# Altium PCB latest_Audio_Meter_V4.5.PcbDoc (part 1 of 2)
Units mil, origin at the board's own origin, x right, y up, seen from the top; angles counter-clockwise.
Board outline 2756.14 x 2519.69 mil, 2 copper layers (Top Layer, Bottom Layer), stack 57.087 mil thick; 115 components, 61 nets, 352 pads, 1177 vias.
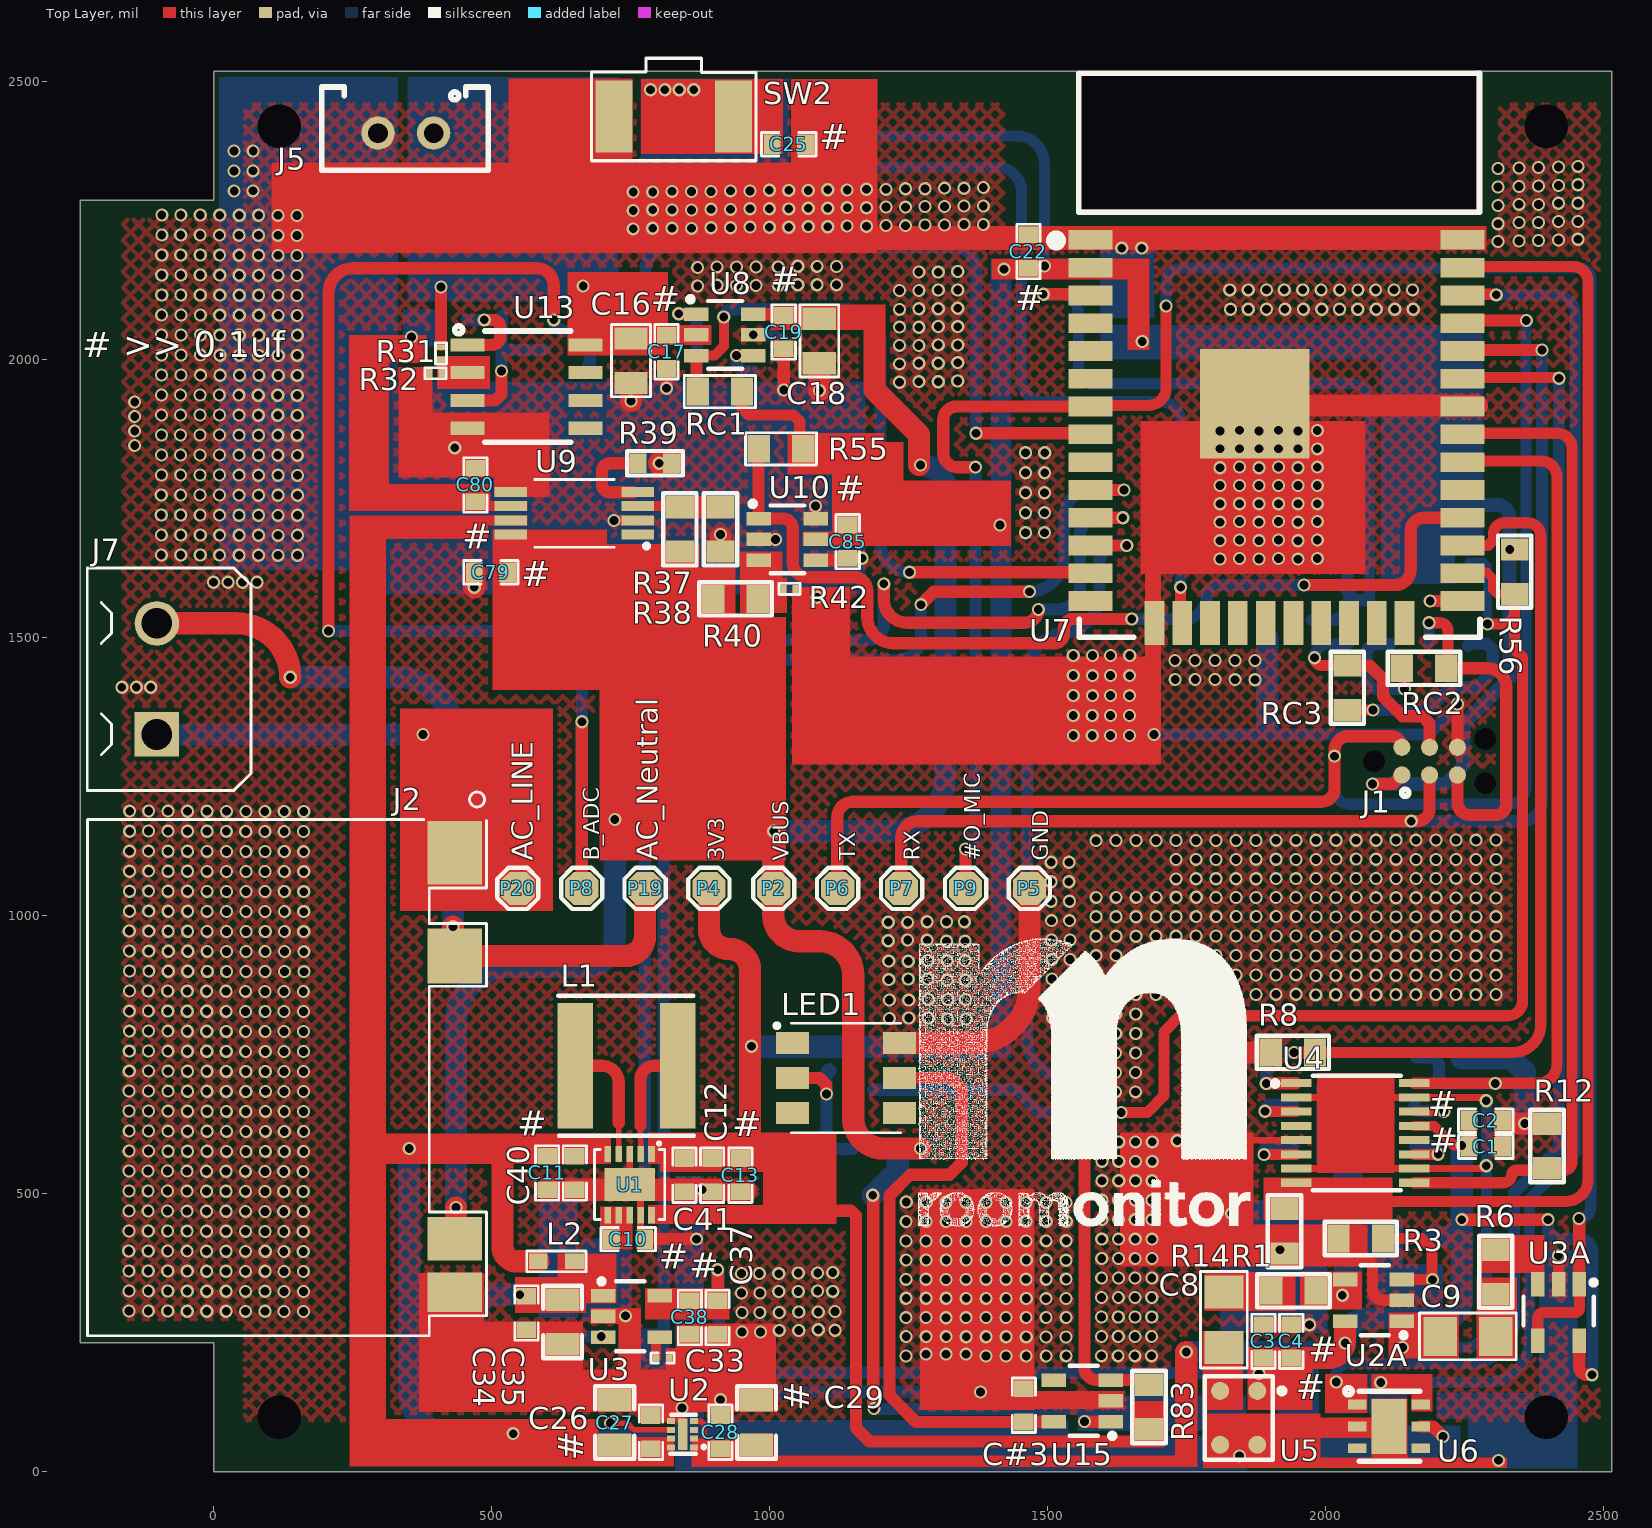
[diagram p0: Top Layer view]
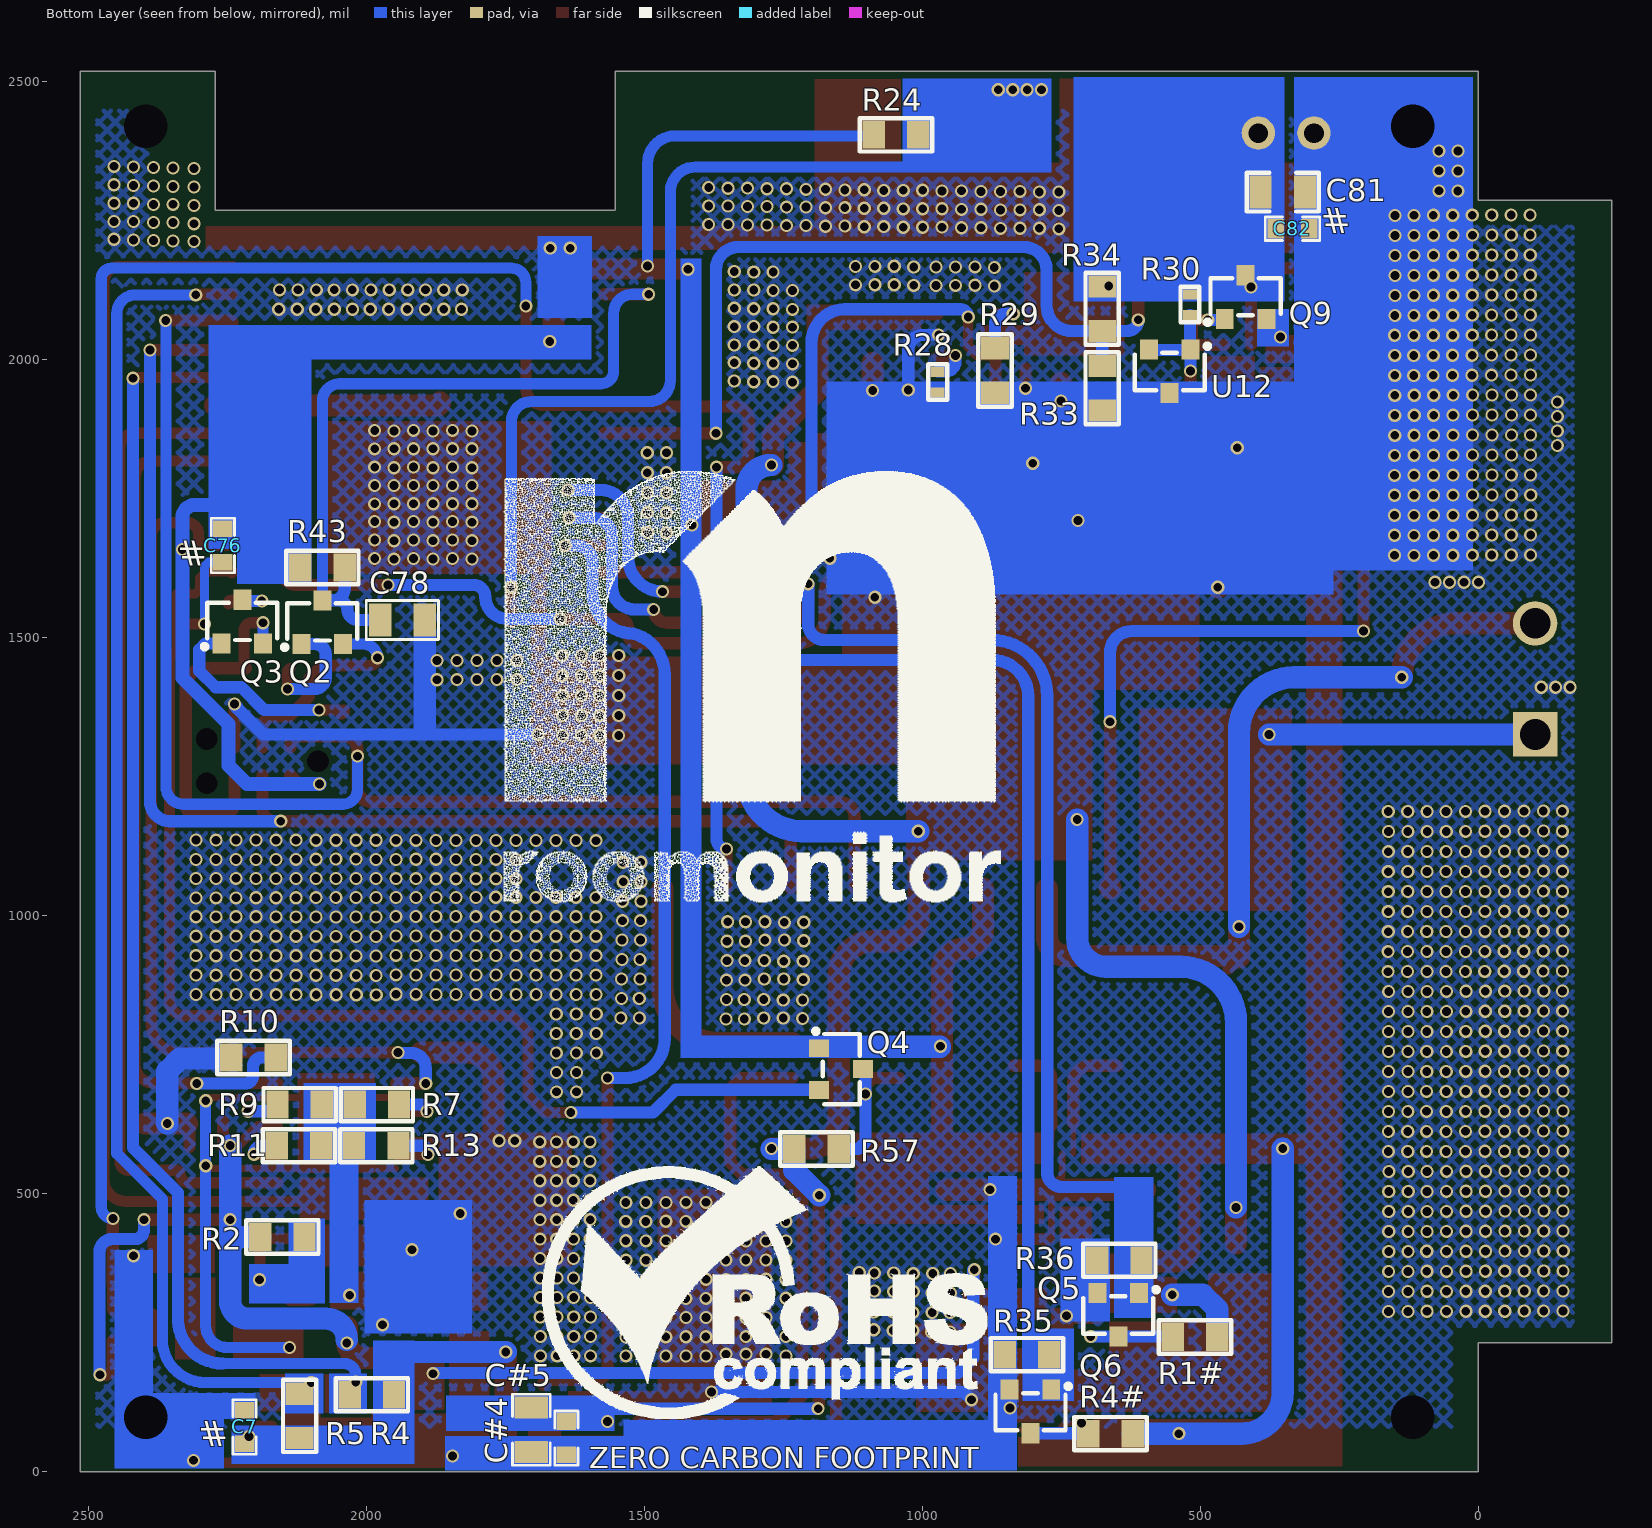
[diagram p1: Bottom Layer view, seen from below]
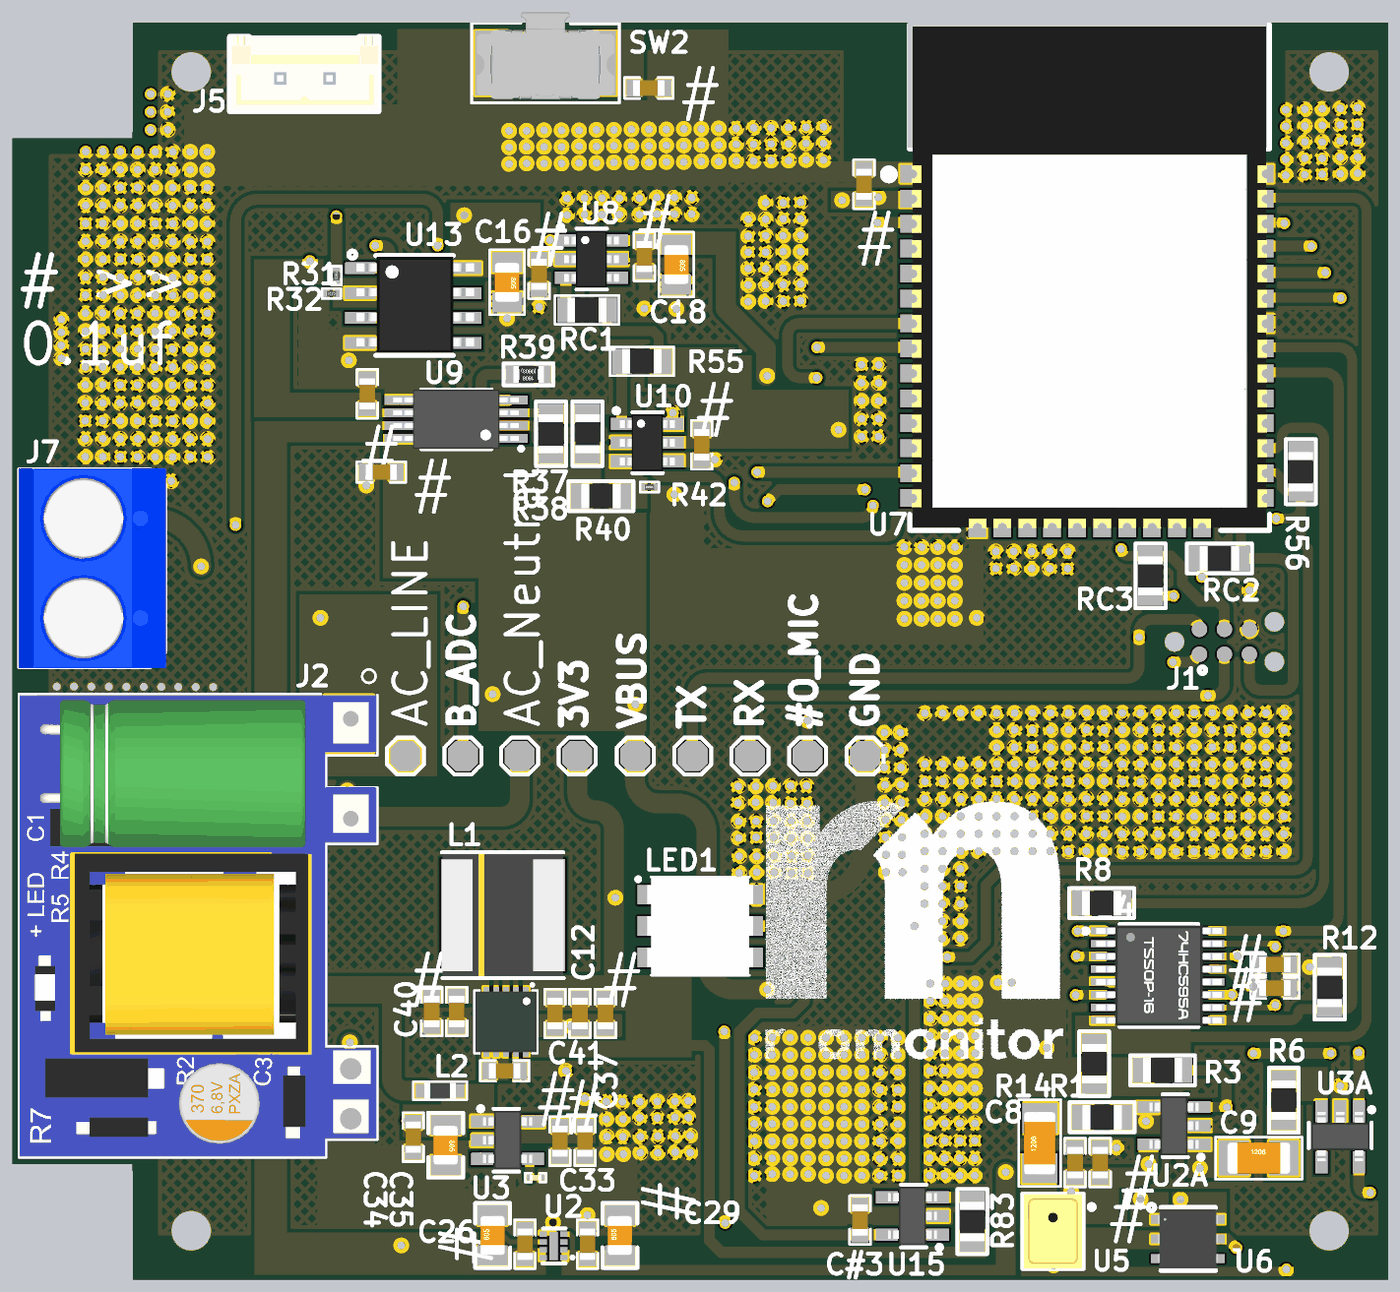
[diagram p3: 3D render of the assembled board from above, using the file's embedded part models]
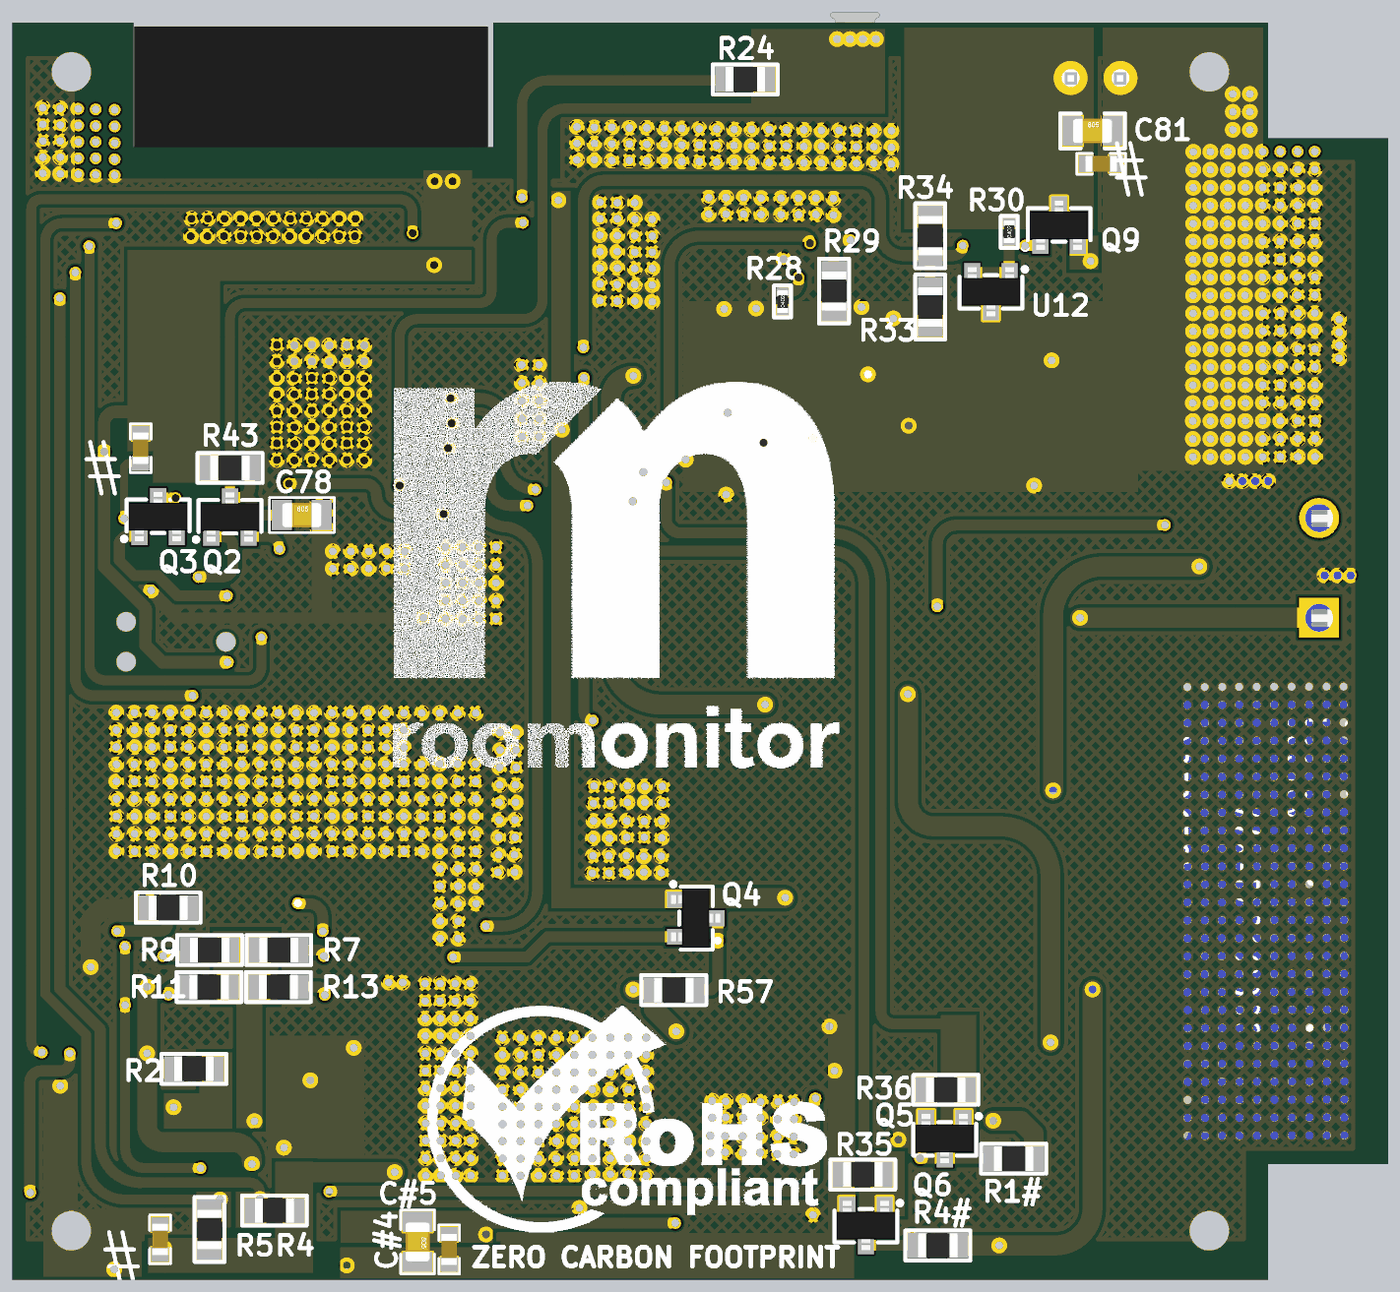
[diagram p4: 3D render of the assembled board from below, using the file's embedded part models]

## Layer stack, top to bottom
Top Solder: solder mask 2.7559, Solder Resist, Dk 3.5
Top Layer: signal copper 13.7795
Dielectric 1: dielectric 29.5276, FR-4, Dk 4.8
Bottom Layer: signal copper 13.7795
Bottom Solder: solder mask 3.1496, Solder Resist, Dk 3.5

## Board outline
-240.16,231.28 -240.16,2287.03 0,2287.03 0,2519 1553,2519 1553,2269 2273,2269 2273,2519 2515.98,2519 2515.98,-0.68 0,-0.69 0,231.28

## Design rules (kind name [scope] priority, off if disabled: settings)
Clearance [All] p1: gap=7 ignorepadtopadclearanceinfootprint=FALSE except(3: Arc-SMDPad Track-SMDPad SMDPad-SMDPad)
ComponentClearance [All] p1: gap=0 collisioncheckmode=3 verticalgap=0 showdistances=FALSE
MinimumSolderMaskSliver [All] p1: minsoldermaskwidth=0
PolygonConnect [All] p1: connectstyle=Direct reliefconductorwidth=10 reliefentries=4 polygonreliefangle="90 Angle" airgapwidth=10
RoutingVias [All] p1: holewidth=15.75 width=23.62 viastyle="Through Hole" minholewidth=15.75 minwidth=23.62 maxholewidth=28 maxwidth=50
SilkToSilkClearance [All] p1: silktosilkclearance=0
SilkToSolderMaskClearance [IsPad] p1: minsilkscreentomaskgap=0 clearancetoexposedcopper=TRUE
SolderMaskExpansion [All] p1: expansion=4
Width [All] p1: maxlimit=40 minlimit=8 preferedwidth=22
26 further rules are at their usual default settings.

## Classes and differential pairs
component class U_SourceSelector_Section: C79 C80 C85 R37 R38 R39 R40 R42 R55 U9 U10
component class U_Supply_Section: J2
component class U_Sensor_Section: C7 C#3 C#4 C#5 LED1 R4 R5 R83 U6 U15
component class U_Power_Section: C10 C11 C12 C13 C26 C27 C28 C29 C33 C34 C35 C37 C38 C40 C41 L1 L2 Q5 Q6 R1# R4# R35 R36 U1 U2 U3
component class U_Controller_Section: C22 C25 C76 C78 Q2 Q3 Q4 R24 R43 R56 R57 RC2 RC3 SW2 U7
component class U_Connector_Section: C81 C82 J1 J5 J7 P2 P4 P5 P6 P7 P19 P20
component class "U_Battery management Section": C16 C17 C18 C19 P8 Q9 R28 R29 R30 R31 R32 R33 R34 RC1 U8 U12 U13
component class U_Audio_Section: C1 C2 C3 C4 C8 C9 P9 R1 R2 R3 R6 R7 R8 R9 R10 R11 R12 R13 R14 U2A U3A U4 U5

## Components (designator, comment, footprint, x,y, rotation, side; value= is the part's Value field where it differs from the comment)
C1 "0.1uF" Cap0603 2289,584 r0 top
C2 "0.1uF" Cap0603 2289,631 r0 top
C3 "0.1uF" Cap0603 1889,234 r90 top
C4 "0.1uF" Cap0603 1939,234 r90 top
C7 "0.1uF" Cap0603 2220,80 r90 bottom
C8 "1206YC105K4T2A" Cap1206 1818,273 r90 top
C9 "1206YC105K4T2A" Cap1206 2257,243 r0 top
C10 "0.1uF" Cap0603 746,418 r0 top
C11 "0.1uF" Cap0603 600,537 r270 top
C12 "10uF" Cap0603 897,533 r270 top
C13 "0.1uF" Cap0603 948,533 r270 top
C16 "1uF" Cap0805#1 751,1998.57 r270 top
C17 "0.1uF" Cap0603 815,2014.57 r270 top
C18 "1uF" Cap0805#1 1090,2034 r270 top
C19 "0.1uF" Cap0603 1026,2050 r270 top
C22 "0.1uF" Cap0603 1466,2195 r90 top
C25 "0.1uF" Cap0603 1035,2388 r0 top
C26 "0.1uF" Cap0603 787,70.56 r90 top
C27 "1uF" Cap0805#2 722,88 r90 top
C28 "0.1uF" Cap0603 912,70.56 r90 top
C29 "1uF" Cap0805#2 977,88 r90 top
C33 "10nF" "CAP 0201" 808,204 r0 top
C34 "10uF" Cap0603 563,285 r270 top
C35 "1uF" Cap0805#2 628,269 r270 top
C37 "10uF" Cap0603 907,277 r270 top
C38 "0.1uF" Cap0603 857,277 r270 top
C40 "10uF" Cap0603 650,537 r270 top
C41 "10uF" Cap0603 847,533 r270 top
C76 "0.1uF" Cap0603 2259,1666 r270 bottom
C78 "1uF" Cap0805#1 1936,1532 r180 bottom
C79 "0.1uF" Cap0603 499,1618 r180 top
C80 "0.1uF" Cap0603 471,1775 r90 top
C81 "4.7UF" Cap0805#2 352,2302 r180 bottom
C82 "0.1uF" Cap0603 334.56,2236 r180 bottom
C85 "0.1uF" Cap0603 1141,1673 r270 top
C#3 "0.1uF" Cap0603 1458,119 r90 top
C#4 "1uF" Cap0805#2 1704,75 r270 bottom
C#5 "0.1uF" Cap0603 1641,60 r270 bottom
J1 "TC2030-IDC" TC2030-IDC 2188,1278 r0 top
J2 "SMD Header" "SMD Header" 434.08,721 r90 top
J5 "B2B-EH-A(LF)(SN)" B2B-EH-A(LF)(SN) 346,2408 r180 top
J7 "Terminal Block 2POS" "Terminal Block 2P" -102,1326 r90 top
L1 "NR6028T1R5N" NR6028T1R5N 743,730 r0 top
L2 "BLM18SG121TN1D" "IND 0603" 617,378 r0 top
LED1 "COM-11821" COM-11821 1138,708 r0 top locked
P2 "TEST POINT" "TEST POINT" 1007.75,1049 r180 top
P4 "TEST POINT" "TEST POINT" 891.38,1049 r0 top
P5 "TEST POINT" "TEST POINT" 1468,1049 r0 top
P6 "TEST POINT" "TEST POINT" 1122.81,1049 r0 top
P7 "TEST POINT" "TEST POINT" 1237.88,1049 r0 top
P8 "TEST POINT" "TEST POINT" 662.56,1049 r90 top
P9 "TEST POINT" "TEST POINT" 1352.94,1049 r270 top
P19 "TEST POINT" "TEST POINT" 776.31,1049 r270 top
P20 "TEST POINT" "TEST POINT" 547.5,1049 r0 top
Q2 "MMBT2222A-7-F" SOT-23 2080,1528 r180 bottom
Q3 "MMBT2222A-7-F" SOT-23 2224,1529 r180 bottom
Q4 "BSS138LT1G" SOT-23 1147,724 r270 bottom
Q5 "BSS138LT1G" SOT-23 648,282 r0 bottom
Q6 "BSS138LT1G" SOT-23 806,108 r0 bottom
Q9 "PMV65XP,215" SOT-23 419,2113 r180 bottom
R1 "1K" "RES 0805" 1943,325 r0 top
R1# "10K" "RES 0805" 510,242 r180 bottom
R2 "10K" "RES 0805" 2152,422 r0 bottom
R3 "10K" "RES 0805" 2064,419 r180 top
R4 "10K" "RES 0805" 1991,138 r180 bottom
R4# "10K" "RES 0805" 662,68 r180 bottom
R5 "10K" "RES 0805" 2121,100 r270 bottom
R6 "1K" "RES 0805" 2307,359 r270 top
R7 "47K" "RES 0805" 1982,660 r0 bottom
R8 "10K" "RES 0805" 1942,754 r0 top
R9 "100K" "RES 0805" 2121,660 r180 bottom
R10 "10K" "RES 0805" 2204,745 r180 bottom
R11 "220K" "RES 0805" 2122,586 r180 bottom
R12 "10K" "RES 0805" 2399,585.56 r270 top
R13 "470K" "RES 0805" 1983,586 r0 bottom
R14 "10K" "RES 0805" 1927,432 r90 top
R24 "10K" "RES 0805" 1048,2405 r0 bottom
R28 "665R" Res0402 973,1960 r90 bottom
R29 "10K" "RES 0805" 870,1981 r90 bottom
R30 "30.9K" Res0402 519,2099.5 r90 bottom
R31 "28K" Res-0201 409.17,2011.83 r90 top
R32 "20K" Res-0201 399.17,1976 r180 top
R33 "1M" "RES 0805" 677,1949 r270 bottom
R34 "1M" "RES 0805" 677,2092 r90 bottom
R35 "10K" "RES 0805" 812.33,210 r0 bottom
R36 "10K" "RES 0805" 646,380 r0 bottom
R37 "10K" "RES 0805" 839,1695 r270 top
R38 "10K" "RES 0805" 912,1695 r90 top
R39 "400R" Res0603 794,1814 r0 top
R40 "10K" "RES 0805" 939,1570 r180 top
R42 "20K" Res-0201 1036.17,1588 r0 top
R43 "10K" "RES 0805" 2080,1626.44 r0 bottom
R55 "10K" "RES 0805" 1021,1840 r180 top
R56 "10K" "RES 0805" 2341,1619 r270 top
R57 "10K" "RES 0805" 1191,580 r180 bottom
R83 "10K" "RES 0805" 1683,116 r90 top
RC1 "10K" "RES 0805" 911,1943 r0 top
RC2 "10K" "RES 0805" 2178,1445 r0 top
RC3 "10K" "RES 0805" 2040,1410 r90 top
SW2 "Switch" KSS221GLFS 828,2438 r180 top
U1 "TPS63031DSKR" TPS63031DSKR 748.63,516.12 r270 top
U2 "NCP186AMX330TAG" NCP186AMX330TAG 844,67 r180 top
U2A "OPA344NA/250" SOT23-5 2087,308 r180 top locked
U3 "LP2985A-33DBVT" SOT23-5 752,279 r0 top
U3A "OPA344NA/250" SOT23-5 2420,286 r270 top locked
U4 "ADG712BRUZ-REEL" 16-TSSOP 2057,609 r0 top locked
U5 "SPU0410HR5H-PB" SPU0410HR5H-PB 1811.07,145 r0 top locked
U6 "SI7021-A20-GM1R" SI7021-A20-GM1R 2115,81 r0 top
U7 "ESP32-WROOM-32 (16MB)" "ESP32-WROOM-32 (16MB)" 1912.65,1871.31 r0 top
U8 "BQ21040DBVR" SOT-23-6 920,2045 r0 top
U9 "TPS2111APWR" 8-TSSOP 649,1724 r180 top
U10 "TPS3711DDCT" SOT-23-6 1032,1677 r0 top
U12 "TLV431BFTA" SOT-23 555.6,1979.63 r0 bottom
U13 "LM393DT" LM393DT 563,1952 r0 top
U15 "MIC2004-0.5YM5-TR" SOT23-5 1563,127 r180 top

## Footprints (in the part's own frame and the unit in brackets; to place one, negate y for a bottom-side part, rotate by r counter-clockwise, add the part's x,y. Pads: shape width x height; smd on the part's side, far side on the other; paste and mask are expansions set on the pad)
8-TSSOP [mm]
  rect 1.5x0.45 smd: 1(-2.9,0.975) 2(-2.9,0.325) 3(-2.9,-0.325) 4(-2.9,-0.975) 5(2.9,-0.975) 6(2.9,-0.325) 7(2.9,0.325) 8(2.9,0.975)
  silkscreen extent -3.38,-1.55 1.8,1.57, body extent -3.2,-1.5 3.2,1.5, height 1.2
16-TSSOP [mm]
  rect 1.4x0.37 smd: 1(-2.775,2.275) 2(-2.775,1.625) 3(-2.775,0.975) 4(-2.775,0.325) 5(-2.775,-0.325) 6(-2.775,-0.975) 7(-2.775,-1.625) 8(-2.775,-2.275) 9(2.625,-2.275) 10(2.625,-1.625) 11(2.625,-0.975) 12(2.625,-0.325) 13(2.625,0.325) 14(2.625,0.975) 15(2.625,1.625) 16(2.625,2.275)
  silkscreen extent -3.85,-2.62 2.01,2.62, body extent -3.2,-2.55 3.2,2.55, height 1.2
B2B-EH-A(LF)(SN) [mil]
  round 60 hole 35.43: 1(-50,0) 2(50,0)
  silkscreen extent -148,-83 151,67, body extent -148,-86 148,64, height 244
Cap0603 [mil]
  rect 30x35 smd mask+2.36: 1(-30,0) 2(30,0)
  silkscreen extent -49,-21 49,21, body extent -32,-16 31,16, height 34
Cap0805#1 [mil] "SMD 0805"
  rect 40x60 smd: 1(-40,0) 2(40,0)
  silkscreen extent -65,-35 65,35, body extent -39,-25 39,25, height 30
Cap0805#2 [mil] "SMD 0805"
  rect 40x60 smd mask+2.76: 1(-40,0) 2(40,0)
  silkscreen extent -65,-35 65,35, body extent -39,-25 39,25, height 30
Cap1206 [mil] "SMD 1206"
  rect 60x70 smd: 1(-50,0) 2(50,0)
  silkscreen extent -87,-42 87,42, body extent -63,-31 63,32, height 39
"CAP 0201" [mm]
  rect 0.3x0.3 smd: 1(-0.3,0) 2(0.3,0)
  silkscreen extent -0.53,-0.23 0.53,0.23, body extent -0.3,-0.15 0.3,0.15, height 0.28
COM-11821 [mm]
  rect 1.5x1 smd: 1(-2.45,1.6) 2(-2.45,0) 3(-2.45,-1.6) 4(2.45,-1.6) 5(2.45,0) 6(2.45,1.6)
  silkscreen extent -3.26,-2.5 2.5,2.5, body extent -2.7,-2.5 2.7,2.5, height 1.75
"ESP32-WROOM-32 (16MB)" [mm]
  rect 2x0.9 smd: 1(-8.5,8.755) 2(-8.5,7.485) 3(-8.5,6.215) 4(-8.5,4.945) 5(-8.5,3.675) 6(-8.5,2.405) 7(-8.5,1.135) 8(-8.5,-0.135) 9(-8.5,-1.405) 10(-8.5,-2.675) 11(-8.5,-3.945) 12(-8.5,-5.215) 13(-8.5,-6.485) 14(-8.5,-7.755) 25(8.5,-7.755) 26(8.5,-6.485) 27(8.5,-5.215) 28(8.5,-3.945) 29(8.5,-2.675) 30(8.5,-1.405) 31(8.5,-0.135) 32(8.5,1.135) 33(8.5,2.405) 34(8.5,3.675) 35(8.5,4.945) 36(8.5,6.215) 37(8.5,7.485) 38(8.5,8.755)
  rect 0.9x2 smd: 15(-5.58,-8.755) 16(-4.31,-8.755) 17(-3.04,-8.755) 18(-1.77,-8.755) 19(-0.5,-8.755) 20(0.77,-8.755) 21(2.04,-8.755) 22(3.31,-8.755) 23(4.58,-8.755) 24(5.85,-8.755)
  rect 5x5 smd: 39(-0.991,1.27)
  silkscreen extent -10.28,-9.4 9.3,16.38, body extent -8.91,-9.3 9.16,16.24, height 3.01
"IND 0603" [mm]
  rect 0.85x0.7 smd: 1(-0.825,0) 2(0.825,0)
  silkscreen extent -1.36,-0.47 1.35,0.47, body extent -0.8,-0.4 0.8,0.4, height 0.8
KSS221GLFS [mil] "Tactile Switch SPST-NO Side Actuated Surface Mount, Right Angle"
  rect 66.93x130 smd: 1(-107.3,0) 2(107.3,0)
  silkscreen extent -148,-105 148,80, body extent -138,-101 138,72, height 65
LM393DT [mm]
  rect 1.55x0.6 smd: 1(-2.7,1.905) 2(-2.7,0.635) 3(-2.7,-0.635) 4(-2.7,-1.905) 5(2.7,-1.905) 6(2.7,-0.635) 7(2.7,0.635) 8(2.7,1.905)
  silkscreen extent -3.28,-2.54 2.03,2.77, body extent -2.91,-2.41 3.09,2.49, height 1.65
NCP186AMX330TAG [mm]
  rect 0.37x0.28 smd: 1(-0.525,0.6) 2(-0.525,0.2) 3(-0.525,-0.2) 4(-0.525,-0.6) 5(0.525,-0.6) 6(0.525,-0.2) 7(0.525,0.2) 8(0.525,0.6)
  rect 0.44x1.44 smd: 9(0,0)
  silkscreen extent -1.02,-0.89 0.56,0.89, body extent -0.6,-0.8 0.6,0.8, height 0.39
NR6028T1R5N [mm] "FIXED IND 1.5UH 4.2A 20.8 MOHM"
  rect 1.62x5.72 smd: 1(-2.35,0) 2(2.35,0)
  silkscreen extent -3.11,-3.2 3.09,3.2, body extent -3.11,-3.1 3.09,3.1, height 2.79
Res0402 [mil]
  rect 18x25 smd mask+4: 1(-18.5,0) 2(18.5,0)
  silkscreen extent -32,-17 32,17, body extent -23,-11 23,11, height 16
Res0603 [mil]
  rect 30x35 smd: 1(-30,0) 2(30,0)
  silkscreen extent -50,-22 50,22, body extent -31,-17 31,17, height 18
"RES 0805" [mil] "SMD 0805"
  rect 40x50 smd: 1(-40,0) 2(40,0)
  silkscreen extent -65,-30 65,30, body extent -39,-25 39,24, height 24
Res-0201 [mm]
  rect 0.27x0.37 smd: 1(-0.275,0) 2(0.275,0)
  silkscreen extent -0.48,-0.25 0.48,0.25, body extent -0.3,-0.15 0.3,0.15, height 0.29
SI7021-A20-GM1R [mm]
  rect 0.85x0.45 smd: 1(-1.45,1) 2(-1.45,0) 3(-1.45,-1) 4(1.45,-1) 5(1.45,0) 6(1.45,1)
  rect 1.6x2.5 smd: 7(0,0)
  silkscreen extent -2.02,-1.6 1.4,1.76, body extent -1.5,-1.5 1.5,1.5, height 1.22
"SMD Header" [mm]
  rect 2.9x2.5 smd: 1(9.97,0)
  rect 2.5x2.5 smd: 2(5.245,0)
  rect 2x2.5 smd: 3(-7.683,0)
  rect 1.8x2.5 smd: 4(-10.122,0)
  silkscreen extent -12.12,-1.45 12.74,16.79, body extent -12.06,-1.4 11.44,16.75, height 12.59
SOT23-5 [mm] "SOT23-5 Package"
  rect 1.12x0.62 smd: 1(-1.3,0.95) 2(-1.3,0) 3(-1.3,-0.95) 4(1.3,-0.95) 5(1.3,0.95)
  silkscreen extent -1.48,-1.6 0.58,1.71, body extent -1.25,-1.5 1.25,1.5, height 1.09
SOT-23 [mm]
  rect 0.82x0.92 smd: 1(-0.95,-1) 2(0.95,-1) 3(0,1)
  silkscreen extent -1.82,-1.23 1.6,0.86, body extent -1.5,-1.25 1.5,1.25, height 1.1
SOT-23-6 [mm]
  rect 1.12x0.62 smd: 1(-1.3,0.95) 2(-1.3,0) 3(-1.3,-0.95) 4(1.3,-0.95) 5(1.3,0) 6(1.3,0.95)
  silkscreen extent -1.69,-1.55 0.79,1.74, body extent -1.4,-1.45 1.4,1.45, height 1.42
SPU0410HR5H-PB [mm]
  round 0.82 smd: 1(1.7,0) 2(1.7,-2.46) 3(0,-2.46) 4(0,0)
  silkscreen extent -0.71,-3.15 2.95,0.67, body extent -0.62,-3.11 2.33,0.65, height 1.03
TC2030-IDC [mil] "CABLE ADAPTER 6 POS"
  round 30.98 smd: 1(-50,-25) 1(-50,-25) 2(-50,25) 3(0,-25) 4(0,25) 5(50,-25) 6(50,25)
  round 0 hole 39.02: MP5(-100,0) MP6(100,-40) MP7(100,40)
  silkscreen extent -50,-63 -38,-51
"Terminal Block 2P" [mil] "TERMINAL BLOCK 2POS 5.08MM SIDE"
  rect 80x80 hole 55: 1(0,0)
  round 80 hole 55: 2(200,0)
  silkscreen extent -101,-169 299,125, body extent -101,-170 299,125, height 394
"TEST POINT" [mil]
  oct 60x60 smd: 1(0,0)
  silkscreen extent -37,-37 37,37
TPS63031DSKR [mm] "Conv DC-DC 1.8V to 5.5V Non-Inv/Inv/Step Up/Step Down Single-Out 3.3V 0.8A 10-Pin WSON"
  rect 0.75x0.3 smd: 1(-1.4,1) 2(-1.4,0.5) 3(-1.4,0) 4(-1.4,-0.5) 5(-1.4,-1) 6(1.4,-1) 7(1.4,-0.5) 8(1.4,0) 9(1.4,0.5) 10(1.4,1)
  rect 1.5x2.3 smd: 11(0,0)
  silkscreen extent -1.96,-1.6 1.6,1.6, body extent -1.56,-1.55 1.56,1.55, height 0.8

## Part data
C1 C2 C3 C4 C7 C10 C11 C13 C17 C19 C22 C25 C26 C28 C38 C76 C79 C80 C82 C85 C#3 C#5: library part CC0603ZRY5V9BB104, "CAP CER 0.1UF 50V Y5V 0603", Capacitance=100nF, Case/Package=0603, Case Code (Metric)=1608, Dielectric=Y5V, Manufacturer=Yageo, Max Operating Temperature=85°C, Min Operating Temperature=-30°C, Package Quantity=1, Supplier Part Number 1=311-1343-1-ND, Tolerance=80%, Voltage=50V
C8 C9: "CAP CER 1UF 16V X7R 1206", Capacitance=1uF, Case/Package=1206, Case Code (Metric)=3216, Dielectric=X7R, Manufacturer="Kyocera AVX", Max Operating Temperature=125°C, Min Operating Temperature=-55°C, Package Quantity=2000, Ratings=AEC-Q200, Supplier Part Number 1=478-10899-1-ND, Tolerance=10%, Voltage Rating=16V
C12 C34 C37 C40 C41: library part C1608X5R1E106M080AC, "CAP CER 10UF 25V X5R 0603", Case/Package=0603, Case Code (Metric)=1608, Dielectric=X5R, Dielectric Material=Ceramic, Manufacturer=TDK, Max Operating Temperature=85°C, Min Operating Temperature=-55°C, Package Quantity=1, Supplier Part Number 1=445-9015-1-ND, Tolerance=20%, Voltage Rating=25V
C16 C18 C27 C29 C35 C78 C#4: library part CL21B105KOFNNNG, "CAP CER 1UF 16V X7R 0805", Case/Package=0805, Case Code (Metric)=2012, Dielectric=X7R, Manufacturer=Samsung, Max Operating Temperature=125°C, Min Operating Temperature=-55°C, Package Quantity=3000, Supplier Part Number 1=1276-6471-6-ND, Tolerance=10%, Voltage=16V
C33: library part UMK063BJ103KP-F, "CAP CER 10000PF 50V X5R 0201", Case/Package=0201, Manufacturer="Taiyo Yuden", Max Operating Temperature=85°C, Min Operating Temperature=-55°C, Supplier Part Number 1=587-5953-1-ND, Tolerance=10%, Voltage Rating=50V
C81: library part C0805C475K4PACTU, "CAP CER 4.7UF 16V 10% X5R 0805", Capacitance=4.7uF, Case/Package=0805, Dielectric=X5R, Dielectric Material=Ceramic, Manufacturer=KEMET, Max Operating Temperature=85°C, Min Operating Temperature=-55°C, Supplier Part Number 1=36X2756, Tolerance=10%, Voltage=16V
J1: "CABLE ADAPTER 6 POS", Manufacturer=Tag-Connect, Package Quantity=1, Supplier Part Number 1=TC2030-IDC-ND
J2: "According to module demension"
J5: "CONN HEADER VERT 2POS 2.5MM", Color=Natural, Contact Resistance=20mR, Current Rating=3A, Housing Color=White, Manufacturer=JST, Max Operating Temperature=85°C, Max Voltage Rating (AC)=250V, Min Operating Temperature=-25°C, Supplier Part Number 1=455-1611-ND
J7: "TERMINAL BLOCK 2POS 5.08MM SIDE", Manufacturer="TE Connectivity", Manufacturer P/N=1776493-2
L1: "FIXED IND 1.5UH 4.2A 20.8 MOHM", Case/Package=2424, Current Rating=920mA, DC Resistance (DCR)=390mR, Inductance=47uh, Inductance Tolerance=20%, Manufacturer="Taiyo Yuden", Manufacturer Part Number=NR6028T470M, Max Operating Temperature=120°C, Min Operating Temperature=-25°C, Package Quantity=2000, Saturation Current=950mA, Self Resonant Frequency=8MHz, Supplier Part Number 1=587-2104-1-ND, Test Frequency=100kHz
L2: "FERRITE BEAD 120 OHM 0603 1LN", Case/Package=0603, Case Code (Metric)=1608, Current Rating=3A, DC Resistance (DCR)=25mR, Frequency=100MHz, Manufacturer=Murata, Max Operating Temperature=125°C, Min Operating Temperature=-55°C, Package Quantity=1, Supplier Part Number 1=490-3996-1-ND, Tolerance=25%
LED1: "ADDRESS LED DISCRETE SERIAL RGB", Color=Blue,Green,Red, Manufacturer=SparkFun, Supplier Part Number 1=1568-1800-ND
P2 P4 P5 P6 P7 P8 P9 P19 P20: "Test Point ON"
Q2 Q3: "TRANS NPN 40V 0.6A SMD SOT23-3", Case/Package=SOT-23, Collector Base Voltage (VCBO)=75V, Collector Emitter Breakdown Voltage=40V, Collector Emitter Saturation Voltage=1V, Continuous Collector Current=600mA, Current=1A, Emitter Base Voltage (VEBO)=6V, Frequency=300MHz, Manufacturer=Diodes, Max Operating Temperature=150°C, Max Power Dissipation=300mW, Min Operating Temperature=-55°C, Package Quantity=3000, Power Dissipation=350mW, Supplier Part Number 1=MMBT2222A-FDIDKR-ND
Q4 Q5 Q6: "MOSFET N-CH 50V 200MA SOT-23", Case/Package=SOT-23-3, Continuous Drain Current (ID)=200mA, Drain to Source Breakdown Voltage=50V, Drain to Source Resistance=3.5R, Gate to Source Voltage (Vgs)=20V, Input Capacitance=50pF, Manufacturer="ON Semiconductor", Max Operating Temperature=150°C, Max Power Dissipation=225mW, Min Operating Temperature=-55°C, Package Quantity=1, Supplier Part Number 1=BSS138LT1GOSDKR-ND, Threshold Voltage=1.5V
Q9: "MOSFET P-CH 20V 2.8A SOT-23", Manufacturer=Nexperia, Supplier Part Number 1=1727-3124-1-ND
R1 R6: library part ERJ-P06J102V, "RES SMD 1K OHM 5% 1/2W 0805", Case/Package=0805, Case Code (Metric)=2012, Manufacturer=Panasonic, Max Operating Temperature=155°C, Max Power Dissipation=500mW, Min Operating Temperature=-55°C, Package Quantity=1, Resistance=1kR, Supplier Part Number 1=P1.0KADCT-ND, Temperature Coefficient=200ppm/°C, Tolerance=5%, Voltage Rating=400V, Voltage Rating (DC)=150V
R1# R2 R3 R4 R4# R5 R8 R10 R12 R14 R24 R29 R35 R36 R37 R38 R40 R43 R56 R57 R83 RC1 RC2 RC3: library part ERJ-P06J103V, "RES SMD 10K OHM 5% 1/2W 0805", Case/Package=0805, Case Code (Metric)=2012, Manufacturer=Panasonic, Max Operating Temperature=155°C, Max Power Dissipation=500mW, Min Operating Temperature=-55°C, Package Quantity=1, Resistance=10kR, Supplier Part Number 1=P10KADCT-ND, Temperature Coefficient=200ppm/°C, Tolerance=5%, Voltage Rating=400V, Voltage Rating (DC)=150V
R7: library part CRCW080547K0FKEAHP, "RES SMD 47K OHM 1% 1/3W 0805", Case/Package=0805, Case Code (Metric)=2012, Manufacturer=Vishay, Max Operating Temperature=155°C, Max Power Dissipation=333mW, Min Operating Temperature=-55°C, Package Quantity=10, Power Rating=330mW, Resistance=47kR, Temperature Coefficient=100ppm/°C, Tolerance=1%, Voltage Rating=150V
R9: library part ERJ-P06J104V, "RES SMD 100K OHM 5% 1/2W 0805", Case/Package=0805, Case Code (Metric)=2012, Manufacturer=Panasonic, Max Operating Temperature=155°C, Max Power Dissipation=250mW, Min Operating Temperature=-55°C, Package Quantity=5000, Power Rating=500mW, Resistance=100kR, Supplier Part Number 1=P100KADCT-ND, Temperature Coefficient=200ppm/°C, Tolerance=5%, Voltage Rating=400V, Voltage Rating (DC)=150V
R11: library part ERJ-P06J224V, "RES SMD 220K OHM 5% 1/2W 0805", Case/Package=0805, Case Code (Metric)=2012, Manufacturer=Panasonic, Max Operating Temperature=155°C, Max Power Dissipation=500mW, Min Operating Temperature=-55°C, Package Quantity=1, Resistance=220kR, Supplier Part Number 1=P220KADCT-ND, Temperature Coefficient=200ppm/°C, Tolerance=5%, Voltage Rating=150V
R13: library part CRCW0805470KFKEAHP, "RES SMD 470K OHM 1% 1/3W 0805", Case/Package=0805, Case Code (Metric)=2012, Manufacturer="Vishay Dale", Max Operating Temperature=155°C, Max Power Dissipation=500mW, Min Operating Temperature=-55°C, Package Quantity=5000, Power Rating=330mW, Resistance=470kR, Supplier Part Number 1=541-470KTCT-ND, Temperature Coefficient=100ppm/°C, Tolerance=1%
R28: library part RC0402FR-07665RL, "RES SMD 665 OHM 1% 1/16W 0402", Case/Package=0402, Case Code (Metric)=1005, Manufacturer=Yageo, Max Operating Temperature=155°C, Max Power Dissipation=63mW, Min Operating Temperature=-55°C, Power Rating=62.5mW, Resistor Type="Thick Film", Supplier Part Number 1=YAG3208CT-ND, Temperature Coefficient=100ppm/°C, Tolerance=1%, Voltage Rating=50V
R30: library part AC0402FR-0730K9L, "RES SMD 30.9K OHM 1% 1/16W 0402", Case/Package=0402, Case Code (Metric)=1005, Manufacturer=Yageo, Max Operating Temperature=155°C, Max Power Dissipation=63mW, Min Operating Temperature=-55°C, Power Rating=62.5mW, Resistance=30.9kR, Supplier Part Number 1=AC0402FR-0730K9L-ND, Temperature Coefficient=100ppm/°C, Tolerance=1%, Voltage Rating=50V
R31: library part AC0201FR-0728KL, "RES SMD 28K OHM 1% 1/20W 0201", Case/Package=0201, Manufacturer=Yageo, Max Operating Temperature=155°C, Max Power Dissipation=50mW, Min Operating Temperature=-55°C, Resistance=28kR, Resistor Type="Thick Film", Supplier Part Number 1=YAG5186CT-ND, Temperature Coefficient=200ppm/°C, Tolerance=1%
R32 R42: library part AC0201FR-0720KL, "RES SMD 20K OHM 1% 1/20W 0201", Case/Package=0201, Case Code (Metric)=0603, Manufacturer=Yageo, Max Operating Temperature=155°C, Max Power Dissipation=50mW, Min Operating Temperature=-55°C, Resistance=20kR, Resistor Type="Thick Film", Supplier Part Number 1=YAG3419CT-ND, Temperature Coefficient=200ppm/°C, Tolerance=1%
R33 R34: library part ERJ-P06J105V, "RES SMD 1M OHM 5% 1/2W 0805", Case/Package=0805, Case Code (Metric)=2012, Manufacturer=Panasonic, Max Operating Temperature=155°C, Max Power Dissipation=500mW, Min Operating Temperature=-55°C, Package Quantity=1, Resistance=1MR, Supplier Part Number 1=P1.0MADCT-ND, Temperature Coefficient=200ppm/°C, Tolerance=5%, Voltage Rating=400V, Voltage Rating (DC)=150V
R39: library part PAT0603E4000BST1, "RES SMD 400 OHM 0.1% 0.15W 0603", Case/Package=0603, Case Code (Metric)=1608, Manufacturer="Vishay Dale Thin Film", Max Operating Temperature=155°C, Max Power Dissipation=150mW, Min Operating Temperature=-55°C, Package Quantity=1, Resistor Type="Thin Film", Supplier Part Number 1=PAT400ACT-ND, Temperature Coefficient=25ppm/°C, Tolerance=0.1%, Voltage Rating=75V
R55: library part ERJ-P06J103V, "RES SMD 10K OHM 5% 1/2W 0805", Case Code (Imperial)=0805, Case Code (Metric)=2012, Manufacturer=Panasonic, Max Operating Temperature=155°C, Max Power Dissipation=500mW, Min Operating Temperature=-55°C, Package Quantity=1, Resistance=10kR, Supplier Part Number 1=P10KADCT-ND, Temperature Coefficient=200ppm/°C, Tolerance=5%, Voltage Rating=400V, Voltage Rating (DC)=150V
SW2: library part KSS221GLFS, "Tactile Switch SPST-NO Side Actuated Surface Mount, Right Angle", Contact Current Rating=50mA, Contact Resistance=100mR, Insulation Resistance=1GR, IP Rating=IP40, Manufacturer="ITT C&K", Max Operating Temperature=85°C, Max Voltage Rating (DC)=32V, Min Operating Temperature=-40°C, Operating Force=2N, Package Quantity=1, Power Rating=1W, Supplier Part Number 1=401-1097-6-ND
U1: "Conv DC-DC 1.8V to 5.5V Non-Inv/Inv/Step Up/Step Down Single-Out 3.3V 0.8A 10-Pin WSON", Manufacturer="Texas Instruments", Max Input Voltage=5.5V, Max Operating Temperature=85°C, Max Output Current=800mA, Min Input Voltage=1.8V, Min Operating Temperature=-40°C, Min Output Voltage=3.3V, Package Quantity=3000, Quiescent Current=25uA, Supplier Part Number 1=TPS63031DSKR**MULT1, Switching Frequency=2.4MHz
U2: "IC REG LINEAR 3.3V 1A 8XDFN", Dropout Voltage=95mV, Manufacturer="ON Semiconductor", Max Operating Temperature=125°C, Min Current Limit=1.1A, Min Operating Temperature=-40°C, Output Current=1A, Output Voltage=3.3V, Supplier Part Number 1=NCP186AMX330TAGOSCT-ND
U2A U3A: "IC OPAMP GP 1 CIRCUIT SOT23-5", Case/Package=SOT-23, Input Bias Current=10pA, Input Offset Voltage (Vos)=1mV, Manufacturer="Texas Instruments", Max Operating Temperature=85°C, Max Supply Voltage=5.5V, Min Operating Temperature=-40°C, Min Supply Voltage=2.7V, Nominal Supply Current=250uA, Output Current per Channel=15mA, Package Quantity=250, Power Supply Rejection Ratio (PSRR)=90.46dB, Quiescent Current=250mA, Supplier Part Number 1=OPA344NACT-ND, Voltage Gain=122dB
U3: "IC REG LINEAR 3.3V 150MA SOT23-5", Case/Package=SOT-23, Dropout Voltage=280mV, Input Bias Current=850uA, Manufacturer="Texas Instruments", Max Input Voltage=16V, Max Operating Temperature=125°C, Max Output Current=150mA, Min Input Voltage=2.2V, Min Operating Temperature=-40°C, Nominal Output Voltage=3.3V, Output Voltage Accuracy=1%, Package Quantity=1, Supplier Part Number 1=296-26127-1-ND
U4: "IC SWITCH QUAD SPST 16TSSOP", Case/Package=TSSOP, High Level Output Current=30mA, Manufacturer="Analog Devices", Max Operating Temperature=85°C, Max Power Dissipation=5uW, Max Supply Current=1uA, Max Supply Voltage=5.5V, Min Operating Temperature=-40°C, Min Supply Voltage=1.8V, On-State Resistance=4R, Operating Supply Current=1nA, Package Quantity=1, Power Dissipation=430mW, Supplier Part Number 1=ADG712BRUZ-REELCT-ND
U5: "SPU-TOP MIC IOT FOCUSED MIC", Manufacturer=Knowles, Operating Supply Current=250uA, Operating Supply Voltage=3.6V, Package Quantity=1200, Supplier Part Number 1=423-1138-1-ND
U6: "SENS HUMID/TEMP 3.6V I2C 2% 6DFN", Manufacturer="Silicon Labs", Max Operating Temperature=85°C, Min Operating Temperature=-40°C, Supplier Part Number 1=336-4380-1-ND
U7: "WIFI MODULE 128MBITS SPI FLASH", Case/Package=SMD/SMT, Frequency=2.5GHz, Manufacturer="Espressif Systems", Manufacturer Part Number=ESP32-WROOM-32D(16MB), Max Operating Temperature=85°C, Min Operating Temperature=-40°C, Supplier Part Number 1=356-ES32WROOM32D16MB
U8: "IC BAT CHG LI-ION 1 CELL SOT23-6", Battery Pack Voltage=4.2V, Case/Package=SOT-23-6, Manufacturer="Texas Instruments", Max Charge Current=800mA, Max Operating Temperature=125°C, Max Supply Voltage=6.45V, Min Operating Temperature=0°C, Supplier Part Number 1=296-47315-1-ND
U9: "IC OR CTRLR SRC SELECT 8TSSOP", Case/Package=TSSOP, Current - Output 2=1.25A, Manufacturer="Texas Instruments", Max Input Voltage=5.5V, Max Operating Temperature=85°C, Max Power Dissipation=387mW, Min Input Voltage=2.8V, Min Operating Temperature=-40°C, Nominal Supply Current=55uA, On-State Resistance=84mR, Output Voltage=6V, Package Quantity=1, Supplier Part Number 1=296-16936-1-ND
U10: "IC SUPERVISOR 1 CHANNEL TSOT23-6", Case/Package=SOT-23-6, Manufacturer="Texas Instruments", Max Operating Temperature=125°C, Max Supply Voltage=36V, Min Operating Temperature=-40°C, Min Supply Voltage=1.8V, Number of Voltages Monitored=1, Quiescent Current=7uA, Supplier Part Number 1=296-43315-1-ND, Threshold Voltage=400mV
U12: "IC VREF SHUNT 18V 0.5% SOT23", Case/Package=SOT-23, Cathode Current=100uA, Manufacturer="Diodes Zetex", Max Input Voltage=20V, Max Operating Temperature=125°C, Max Output Current=15mA, Max Output Voltage=18V, Min Operating Temperature=-40°C, Min Output Voltage=1.24V, Package Quantity=1, Supplier Part Number 1=TLV431BFCT-ND, Tolerance=0.5%
U13: "IC COMPARATOR LP DUAL 8-SOIC", Case/Package=SO, Dual Supply Voltage=9V, Input Bias Current=250nA, Input Offset Voltage (Vos)=5mV, Manufacturer=STMicroelectronics, Max Dual Supply Voltage=18V, Max Operating Temperature=70°C, Max Power Dissipation=710mW, Max Supply Current=1mA, Max Supply Voltage=36V, Min Dual Supply Voltage=1V, Min Operating Temperature=0°C, Min Supply Voltage=2V, Natural Thermal Resistance=125°C/W, Operating Supply Voltage=28V, Output Current=18mA, Output Current per Channel=100pA, Package Quantity=2500, Quiescent Current=2.5mA, Supplier Part Number 1=497-1593-1-ND, Voltage Gain=106.02dB
U15: "IC PWR SWITCH P-CHAN 1:1 SOT23-5", Manufacturer=Microchip, Supplier Part Number 1=576-2582-1-ND

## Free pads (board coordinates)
  round 60 hole 78.74: MH2(118.11,97.43) MH3(118.11,2420.26) MH3(2397.87,97.43) MH3(2397.87,2420.26)

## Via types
v1: diameter 23.62, hole 15.75, Top Layer to Bottom Layer, 917 vias
v2: diameter 23.62, hole 15.75, Top Layer to Bottom Layer, tented both sides, 260 vias

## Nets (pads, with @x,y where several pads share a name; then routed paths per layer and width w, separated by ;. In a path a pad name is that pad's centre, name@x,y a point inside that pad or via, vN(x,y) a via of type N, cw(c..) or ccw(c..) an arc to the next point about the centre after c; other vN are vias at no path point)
3V3: C12.1 C13.1 C22.1 C41.1 C76.1 C85.1 J1.1 P4.1 Q4.1 R24.2 R43.2 R55.1 R56.1 R83.1 RC1.2 U1.1 U1.10 U7.2 U10.5 | length 3943.5
  Top Layer w20: RC1.2@951,1943 951,1912.72 962.72,1901 1043,1901 1054.72,1889.28 1054.72,1846.28 R55.1@1061,1840 ; C85.1@1141,1703 1141,1783 ; v1(1495,2169) 1571.71,2169 cw(c1571.71,2168) 1572.71,2168 1627,2168 cw(c1627,2123) 1672,2123 1672,2034 cw(c1671,2034) v1(1671,2033)
  Top Layer w22: 1096,469 1147,469 1156,460 1156,78 1180,54 1659,54 ; v1(2085,1237) 2122,1237 J1.1@2138,1253
  Top Layer w40: P4.1@891.38,1049 891.38,976.3 ccw(c927.67,976.3) 927.67,940 cw(c927.67,902.67) 965,902.67 965,579 ccw(c967,579) 967,577
  Bottom Layer w12: 2238,1717 cw(c2245,1717) 2245,1724
  Bottom Layer w20: R24.2@1092,2403 1445.34,2403 cw(c1445.34,2353.34) 1495,2353.34 v1(1495,2169)
  Bottom Layer w22: 2245,1724 2260,1724 ccw(c2260,1739) 2275,1739
  Bottom Layer w25: v1(2085,1237) 2216,1237 2249,1270 2249,1301.83 2248.99,1344.71 2332,1427.72 v1(2332,1659) 2332,1716.34 ccw(c2309.34,1716.34) 2309.34,1739 2275,1739
  Bottom Layer w40: v1@969,764 1416,764
  other v1: 968,765 1415,1703 1422,2163
3V3_Audio: C1.1 C2.1 C3.1 C4.1 C37.1 C38.1 R2.2 U2A.5 U3.5 U3A.5 U4.13 U5.1 | length 2707.2
  Top Layer w18: U4.13@2160.35,621.8 2196.2,621.8 2231.39,586.61 v1(2246,586.61)
  Top Layer w22: C37.1@907,307 v1(907,363) ; v1(2246,453) v1(2401,453) ; C1.1@2259,584 C2.1@2259,631 ; U3A.5@2457.4,234.82 2457.4,187 ccw(c2470.4,187) 2470.4,174 v1(2480,174)
  Top Layer w40: C3.1@1889,204 C4.1@1939,204 2003.98,204 ccw(c2003.98,235.84) 2035.82,235.84 U2A.5@2035.82,259.53
  Bottom Layer w22: v1@909,363 909,204 936,177 1241,177 v1@1881,177 ; v1(2401,453) 2401,435 ccw(c2418,435) 2418,418 2458.06,418 cw(c2458.06,395.06) 2481,395.06 2481,175 cw(c2480,175) v1(2480,174)
  Bottom Layer w40: v1@2036,237 cw(c2074,237) 2074,275 2214,275 ccw(c2214,307) 2246,307 2246,397 ; R2.2@2192,422 2221,422 cw(c2221,397) 2246,397 ; v1(2246,586.61) v1(2246,453) 2246,397
  other v1: 1881,176 2036,231
3V3_SENS: C7.1 C28.1 C29.1 R4.2 R5.2 U2.1 U2.2 U2.4 U6.5 | length 592
  Top Layer w10: U2.4@864.67,90.62 876.38,90.62 882,85 882,46 887.44,40.56 C28.1@912,40.56
  Top Layer w22: C28.1@912,40.56 969.56,40.56 ccw(c969.56,48) C29.1@977,48 ; U6.5@2172.09,81 2194,81 v1(2212,63)
  Top Layer w40: 1750,29 v1(1750,215)
  Bottom Layer w40: v1(1750,215) 1926,215 ; R4.2@1951,138 R4.2@1951,160.45
#12-P: R8.2 U4.1 U7.27 | length 1675.3
  Top Layer w20: R8.2@1982,754 2338,754 ccw(c2338,804) 2388,804 2388,1683.1 ccw(c2364.1,1683.1) 2364.1,1707 2323,1707 ccw(c2323,1687) 2303,1687 2303,1676 2293,1666 U7.27@2247.29,1666
  Top Layer w22: v1(1894,698) 1894,698.57 U4.1@1947.75,698.57 ; v1(1944,754) R8.2@1982,754
  Bottom Layer w22: v1(1894,698) 1894,726.05 cw(c1920.95,726.05) 1920.95,753 v1@1939,753
#12-S: R7.1 U4.3 | length 113.6
  Top Layer w20: v1@1892,647.39 U4.3@1947.75,647.39
  Bottom Layer w22: v1(1892,648) cw(c1904,648) 1904,660 R7.1@1943,660
#13-P: R10.2 U4.16 U7.30 | length 1700.3
  Top Layer w20: U4.16@2160.35,698.57 2383.39,698.57 ccw(c2383.39,732.18) 2417,732.18 2417,1789.51 ccw(c2388.51,1789.51) 2388.51,1818 U7.30@2242,1818
  Bottom Layer w22: R10.2@2164,745 2188.31,745 cw(c2188.31,728.31) 2205,728.31 2205,712 ccw(c2219,712) 2219,698 v1(2306,698)
#13-S: R9.1 U4.14 | length 113.5
  Top Layer w16: U4.14@2160.35,647.39 v1@2214,647.39
  Bottom Layer w22: R9.1@2161,660 ccw(c2173,660) 2173,648 v1(2214,648)
#14-P: R12.2 U4.9 U7.31 | length 1807.4
  Top Layer w20: U4.9@2160.35,519.43 2313,519.43 2320.43,519.43 ccw(c2320.43,535) 2336,535 cw(c2343,535) 2343,542 2399,542 2430,542 ccw(c2430,556) 2444,556 2444,1842 ccw(c2418,1842) 2418,1868 U7.31@2242,1868
#14-S: R11.1 U4.11 | length 91
  Top Layer w20: U4.11@2160.35,570.61 v1(2203.39,570.61)
  Bottom Layer w22: R11.1@2162,586 2185.84,586 ; 2187.84,586 cw(c2187.84,570.61) v1@2203.23,570.61
#15-P: R14.2 U4.8 U7.37 | length 2283.4
  Top Layer w20: 2074,486 2433.73,486 ccw(c2433.73,525.27) 2473,525.27 2473,2140.68 ccw(c2445.68,2140.68) 2445.68,2168 U7.37@2242,2168
#15-S: R13.1 U4.6 | length 118.3
  Top Layer w20: v1@1891.48,570.61 U4.6@1947.75,570.61
  Bottom Layer w22: v1@1889,572 cw(c1903,572) 1903,586 R13.1@1943,586
  other v1: 1890,570
#_OUT_MIC: R1.2 R7.2 R9.2 R11.2 R13.2 U2A.4
  other v1: 2031,317
#O_MIC: P9.1 U3A.1 U3A.4 U7.7 | length 4306.2
  Top Layer w20: U7.7@1572.71,1918 1682,1918 ccw(c1682,1950) 1714,1950 v1(1714,2097) ; U3A.4@2382.6,234.82 2382.6,275.06 cw(c2393.53,275.06) 2393.53,286 2449,286 ccw(c2449,295) 2458,295 2458,337.18 U3A.1@2457.4,337.18
  Top Layer w22: P9.1@1352.75,1049 1353,1049 v1(1353,1120) ; v1(1371,1807) 1338,1807 cw(c1338,1832) 1313,1832 1313,1892.51 cw(c1336.49,1892.51) 1336.49,1916 U7.7@1578,1916 ; U3A.1@2457.4,337.18 v1@2457.4,452.6
  Bottom Layer w20: v1(1714,2097) 1714,2139 cw(c1740,2139) 1740,2165 2459,2165 cw(c2459,2146) 2478,2146 2478,483 2478,476 cw(c2457,476) v1(2457,455)
  Bottom Layer w22: v1(1353,1120) ccw(c1353,1138) 1371,1138 v1(1371,1807)
#OUT_MIC: C9.1 U2A.1 U4.2 U4.7 U4.10 U4.15 | length 1069
  Top Layer w12: U4.7@1947.75,545.02 2013,545 ; U4.2@1947.75,672.98 1998,672.98 ; 2108,672.98 U4.15@2160.35,672.98 2284.02,672.98 cw(c2284.02,667) v1(2290,667) ; 2112,545.02 U4.10@2160.35,545.02 2282.02,545.02 ccw(c2282.02,554) 2291,554 v1@2287,550
  Bottom Layer w20: v1(2139,223) 2251,223 ccw(c2251,262) 2290,262 v1(2290,550) v1(2290,667)
A_REG: Q5.1 R36.1 U7.11 | length 2375.2
  Top Layer w22: v1(1206,1597) 1206,1569 ccw(c1248,1569) 1248,1527 1460,1527 ccw(c1460,1551) v1(1484,1551) ; U7.11@1578,1716 v1(1636,1716)
  Bottom Layer w22: 605,498 cw(c619,498) 619,512 749.84,512 ccw(c749.84,538.16) 776,538.16 776,1396 cw(c876,1396) 876,1496 1177,1496 ccw(c1177,1525) 1206,1525 v1(1206,1597) ; R36.1@606,380 cw(c606,375.4) 610.6,375.4 Q5.1@610.6,321.37 ; v1(1484,1551) 1518,1551 ccw(c1518,1592) 1559,1592 1559,1690.17 cw(c1595,1678) 1595,1716 v1(1636,1716)
AC_LINE: J2.1 J7.1 P20.1 | length 523.6
  Top Layer w22: J2.1@436.08,1134.5 ccw(c437.58,1134.5) J2.1@437.58,1133
  Top Layer w40: J2.1@430.58,1133 J2.1@434.08,1133 ; J2.1@434.08,1113.5 J2.1@434.08,1133 ; J2.1@437.58,1133 J2.1@434.08,1133
  Bottom Layer w22: J7.1@-102,1326 ccw(c-92,1326) J7.1@-92,1316
  Bottom Layer w40: J7.1@-102,1326 v1(377,1326)
AC_Neutral: J2.2 J7.2 P19.1 | length 1531.6
  Top Layer w22: J2.2@436.08,934.5 ccw(c474.58,934.5) 436.72,927.5 ccw(c474.58,934.5) J2.2@449.84,905
  Top Layer w40: J7.2@-102,1526 41,1526 cw(c41,1429) v1(138,1429) ; J2.2@431,925 v1(431,980) ; J2.2@434.08,927.5 436.72,927.5 740.85,927.5 ccw(c740.85,962.97) 776.31,962.97 P19.1@776.31,1049
  Bottom Layer w40: v1(138,1429) 331,1429 cw(c331,1329) 391.74,1408.44 cw(c331,1329) 431,1329 v1(431,980)
B_ADC: P8.1 R33.1 R34.1 U7.8 | length 3502.4
  Top Layer w22: v1(207,1512) 207,2120.86 cw(c251.14,2120.86) 251.14,2165 581.17,2165 cw(c581.17,2134.17) 612,2134.17 v1(612,2072) ; P8.1@661.25,1049 P8.1@662.56,1050.31 ; v1@662.56,1349 P8.1@662.56,1050.31 ; P8.1@669,1056.75 P8.1@662.56,1050.31 ; v1(1372,1868) U7.8@1572.71,1868
  Top Layer w40: P8.1@662.56,1049 P8.1@662.56,1050.31
  Bottom Layer w22: v1(207,1512) 623.86,1512 cw(c623.86,1472.86) 663,1472.86 v1(663,1349) ; v1(612,2072) ccw(c632,2072) 632,2052 R34.1@677,2052 ; R33.1@672,1987 677,1992 R34.1@677,2052 ; v1(1372,1868) 1372,2162.27 ccw(c1331.27,2162.27) 1331.27,2203 818,2203 ccw(c818,2162) 777,2162 777,2098 cw(c731,2098) 731,2052 R34.1@677,2052
BATT_IN: C16.1 C17.1 C81.1 C82.1 J5.1 Q9.3 R30.2 R31.2 R34.2 U8.2 U13.8 | length 114.2
  Top Layer w22: R31.2@409.17,2026.65 v1@409.17,2131 ; C16.1@751,2038.57 cw(c757,2038.57) C16.1@757,2044.57 ; C17.1@815,2044.57 C17.1@815,2045
  other v1: 409,2131 665,2133
C_VIN: C34.1 C35.1 L2.2 R1#.2 U3.1 | length 141.8
  Bottom Layer w40: R1#.2@470,242 470,292 496,318 v1(551,318)
CHG: RC1.1 U7.13 U8.3 | length 1262.3
  Top Layer w18: U8.3@868.82,2007.6 901.27,2007.6 918,2024.33 v1(918,2077)
  Top Layer w22: U8.3@868.82,2007.6 868.82,1945.18 ccw(c871,1945.18) RC1.1@871,1943 ; v1(1252,1618) U7.13@1572.71,1618
  Bottom Layer w22: v1(918,2077) cw(c932,2077) 932,2091 1140,2091 cw(c1140,2031) 1200,2031 1200,1670 ccw(c1252,1670) v1(1252,1618)
CLED: LED1.2 Q4.3 R57.2 | length 273.4
  Top Layer w22: LED1.2@1041.54,708 1090,708 1103,695 v1(1103,679)
  Bottom Layer w22: Q4.3@1110.63,721 Q4.3@1107.63,724 1103,719.37 v1(1103,679) 1103,593 1116,580 R57.2@1151,580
